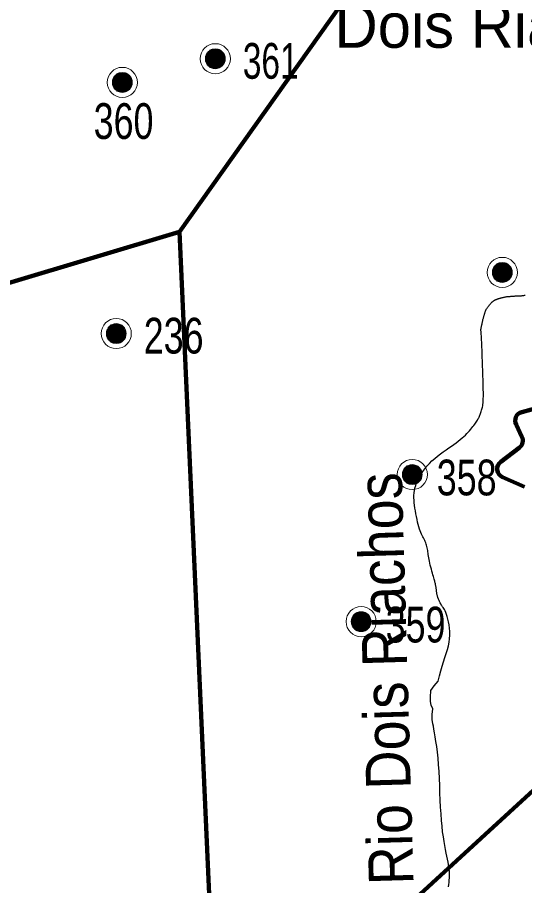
# Model space of a CAD drawing. Extents: x 553962 to 842807, y 8883888 to 9032388.
# Drawn here: x 703268 to 708947, y 8951050 to 8960766 of the extents above; entities that cross this region are included whole.
import ezdxf
from ezdxf.enums import TextEntityAlignment as Align

# ---------------------------------------------------------------- set-up
doc = ezdxf.new("R2010")
doc.units = 0
doc.header["$LTSCALE"] = 160
for name, color, linetype, lineweight in [('21', 7, 'Continuous', 25), ('22', 7, 'Continuous', 35), ('27', 7, 'Continuous', 90), ('32', 7, 'Continuous', 13), ('33', 7, 'Continuous', 13), ('7', 7, 'Continuous', 90)]:
    doc.layers.add(name, color=color, linetype=linetype, lineweight=lineweight)
doc.layers.add('29', color=7, linetype='Continuous')

msp = doc.modelspace()

# ---------------------------------------------------------------- linework, layer by layer
at = {"layer": '21'}
for points in [[(708437, 8956293.7), (708441.3, 8956303.2), (708445.5, 8956313.2), (708449.7, 8956323.7), (708453.8, 8956334.6), (708457.8, 8956345.8), (708461.7, 8956357.3), (708465.4, 8956369), (708468.9, 8956381), (708472.1, 8956393.1), (708475, 8956405.4), (708477.6, 8956418.6), (708479.8, 8956433.5), (708481.7, 8956451.1), (708483.1, 8956472), (708484.1, 8956497.2), (708484.6, 8956527.5), (708484.6, 8956563.7), (708484.1, 8956606.2), (708483.2, 8956654), (708481.8, 8956705.4), (708480.3, 8956759.1), (708478.5, 8956813.4), (708476.7, 8956866.9), (708474.8, 8956918), (708473.1, 8956965.2), (708471.5, 8957007.4), (708470, 8957044.6), (708468.7, 8957077.2), (708467.5, 8957105.9), (708466.3, 8957130.9), (708465.2, 8957152.8), (708464.2, 8957172), (708463.1, 8957189), (708462.1, 8957204.1), (708461.1, 8957217.7), (708460.1, 8957229.8), (708459.3, 8957240.7), (708458.7, 8957250.5), (708458.3, 8957259.4), (708458.2, 8957267.5), (708458.3, 8957275.2), (708458.9, 8957282.4), (708459.7, 8957289.3), (708460.8, 8957296), (708462.1, 8957302.5), (708463.6, 8957308.9), (708465.1, 8957315.2), (708466.7, 8957321.6), (708468.3, 8957328), (708469.8, 8957334.6), (708471.2, 8957341.3), (708472.7, 8957348.2), (708474.1, 8957355.1), (708475.6, 8957362.2), (708477.2, 8957369.4), (708478.8, 8957376.7), (708480.6, 8957384), (708482.5, 8957391.5), (708484.6, 8957398.9), (708486.7, 8957406.3), (708488.8, 8957413.7), (708490.9, 8957421), (708493, 8957428.1), (708495, 8957434.9), (708496.9, 8957441.6), (708498.7, 8957448), (708500.4, 8957454.1), (708502, 8957459.9), (708503.7, 8957465.6), (708505.4, 8957471.2), (708507.2, 8957476.6), (708509.3, 8957482), (708511.6, 8957487.3), (708514.1, 8957492.6), (708516.9, 8957497.9), (708520, 8957503.2), (708523.2, 8957508.4), (708526.6, 8957513.7), (708530.1, 8957518.8), (708533.6, 8957523.9), (708537.2, 8957529), (708540.8, 8957533.9), (708544.4, 8957538.8), (708548.1, 8957543.6), (708551.7, 8957548.3), (708555.4, 8957552.9), (708559.1, 8957557.3), (708562.9, 8957561.7), (708566.8, 8957565.8), (708570.7, 8957569.9), (708574.7, 8957573.8), (708578.7, 8957577.5), (708582.7, 8957581), (708586.8, 8957584.4), (708590.8, 8957587.5), (708594.7, 8957590.5), (708598.6, 8957593.2), (708602.5, 8957595.8), (708606.3, 8957598.1), (708610.1, 8957600.3)], [(708610.1, 8957600.3), (708613.9, 8957602.3), (708617.8, 8957604.2), (708621.9, 8957606), (708626.1, 8957607.8), (708630.4, 8957609.6), (708635, 8957611.3), (708639.8, 8957613.1), (708644.9, 8957614.8), (708650.2, 8957616.6), (708655.9, 8957618.4), (708661.8, 8957620.3), (708668.2, 8957622.2), (708674.8, 8957624.2), (708681.8, 8957626.2), (708689.2, 8957628.3), (708696.9, 8957630.4), (708704.8, 8957632.4), (708713, 8957634.4), (708721.5, 8957636.2), (708730.2, 8957637.9), (708739, 8957639.4), (708747.9, 8957640.7), (708757, 8957641.8), (708766, 8957642.8), (708774.9, 8957643.6), (708783.6, 8957644.3), (708792.1, 8957644.9), (708800.2, 8957645.4), (708807.8, 8957646), (708815, 8957646.5), (708821.7, 8957647), (708828, 8957647.5), (708834, 8957648), (708839.8, 8957648.5), (708845.3, 8957648.9), (708850.7, 8957649.2), (708856.1, 8957649.5), (708861.4, 8957649.7), (708866.8, 8957649.9), (708872.2, 8957650), (708877.6, 8957650.1), (708883.2, 8957650.2), (708888.8, 8957650.3), (708894.5, 8957650.5), (708900.4, 8957650.7), (708906.4, 8957651), (708912.5, 8957651.4), (708918.8, 8957651.9), (708925.2, 8957652.6), (708931.7, 8957653.4), (708938.3, 8957654.5), (708945, 8957655.8), (708951.8, 8957657.4)], [(707956, 8954384.1), (707954.9, 8954391.2), (707953.6, 8954398.5), (707952.2, 8954405.9), (707950.7, 8954413.4), (707949.1, 8954421), (707947.3, 8954428.8), (707945.3, 8954437.1), (707943, 8954446), (707940.4, 8954455.9), (707937.4, 8954466.9), (707933.9, 8954479.4), (707929.9, 8954493.6), (707925.3, 8954509.7), (707920.2, 8954528), (707914.5, 8954548.1), (707908.6, 8954569.4), (707902.5, 8954591.7), (707896.6, 8954614.5), (707890.9, 8954637.2), (707885.6, 8954659.4), (707881, 8954680.8), (707877.1, 8954701), (707873.8, 8954719.9), (707871.1, 8954737.8), (707868.7, 8954754.7), (707866.4, 8954770.9), (707864.2, 8954786.4), (707861.8, 8954801.5), (707859.2, 8954816.2), (707856.2, 8954830.6), (707852.6, 8954844.8), (707848.7, 8954858.9), (707844.3, 8954872.8), (707839.4, 8954886.5), (707834.1, 8954900.2), (707828.4, 8954913.7), (707822.2, 8954927.1), (707815.6, 8954940.5), (707808.6, 8954954.2), (707801.3, 8954968.6), (707793.8, 8954984.1), (707786.2, 8955000.9), (707778.5, 8955019.5), (707770.9, 8955040.3), (707763.3, 8955063.6), (707755.9, 8955089.6), (707748.8, 8955117.9), (707741.9, 8955148), (707735.5, 8955179.4), (707729.4, 8955211.4), (707724, 8955243.5), (707719, 8955275.2), (707714.8, 8955305.8), (707711.3, 8955335.1), (707708.8, 8955363.1), (707707.5, 8955390.3), (707707.6, 8955417.1), (707709.3, 8955443.8), (707713, 8955470.7), (707718.8, 8955498.4), (707727, 8955527), (707737.7, 8955556.9), (707751, 8955587.8), (707766.7, 8955619.4), (707784.9, 8955651.3), (707805.4, 8955683.3), (707828.1, 8955714.8), (707853.1, 8955745.7), (707880.1, 8955775.4), (707909.2, 8955803.8), (707939.8, 8955830.8), (707971.5, 8955856.6), (708003.7, 8955881.1), (708035.9, 8955904.5), (708067.7, 8955926.8), (708098.4, 8955948.1), (708127.7, 8955968.5), (708155, 8955988), (708180.5, 8956006.7), (708204.2, 8956024.7), (708226.2, 8956042.2), (708246.8, 8956059.2), (708265.9, 8956075.9), (708283.8, 8956092.2), (708300.4, 8956108.5), (708316.1, 8956124.6), (708330.7, 8956140.5), (708344.2, 8956156.1), (708356.8, 8956171.3), (708368.4, 8956185.9), (708378.9, 8956199.9), (708388.5, 8956213.1), (708397.1, 8956225.4), (708404.8, 8956236.7), (708411.5, 8956247.1), (708417.6, 8956257), (708423.1, 8956266.3), (708428, 8956275.5), (708432.6, 8956284.5), (708437, 8956293.7)], [(708079.3, 8954060.8), (708071.1, 8954085.7), (708063.2, 8954106.6), (708055.7, 8954124), (708048.6, 8954138.5), (708041.7, 8954150.6), (708035.2, 8954160.9), (708029.1, 8954169.9), (708023.1, 8954178.3), (708017.4, 8954186.5), (708012, 8954195), (708006.8, 8954203.9), (708001.8, 8954213), (707997.2, 8954222.1), (707992.8, 8954231.2), (707988.8, 8954240.2), (707985.1, 8954248.9), (707981.7, 8954257.1), (707978.7, 8954264.9), (707976, 8954272.2), (707973.6, 8954279.2), (707971.6, 8954285.9), (707969.7, 8954292.3), (707968.1, 8954298.6), (707966.8, 8954304.8), (707965.5, 8954311), (707964.5, 8954317.3), (707963.5, 8954323.6), (707962.7, 8954330.1), (707961.9, 8954336.5), (707961.2, 8954343.1), (707960.4, 8954349.7), (707959.7, 8954356.5), (707958.9, 8954363.2), (707958, 8954370.1), (707957.1, 8954377), (707956, 8954384.1)], [(708079.3, 8954060.8), (708071.1, 8954085.7), (708063.2, 8954106.6), (708055.7, 8954124), (708048.6, 8954138.5), (708041.7, 8954150.6), (708035.2, 8954160.9), (708029.1, 8954169.9), (708023.1, 8954178.3), (708017.4, 8954186.5), (708012, 8954195), (708006.8, 8954203.9), (708001.8, 8954213), (707997.2, 8954222.1), (707992.8, 8954231.2), (707988.8, 8954240.2), (707985.1, 8954248.9), (707981.7, 8954257.1), (707978.7, 8954264.9), (707976, 8954272.2), (707973.6, 8954279.2), (707971.6, 8954285.9), (707969.7, 8954292.3), (707968.1, 8954298.6), (707966.8, 8954304.8), (707965.5, 8954311), (707964.5, 8954317.3), (707963.5, 8954323.6), (707962.7, 8954330.1), (707961.9, 8954336.5), (707961.2, 8954343.1), (707960.4, 8954349.7), (707959.7, 8954356.5), (707958.9, 8954363.2), (707958, 8954370.1), (707957.1, 8954377), (707956, 8954384.1)], [(708105.3, 8951136), (708106, 8951160.4), (708105.7, 8951184.6), (708104.4, 8951208.7), (708102.1, 8951233.3), (708098.8, 8951258.8), (708094.7, 8951285.6), (708089.7, 8951314.1), (708083.8, 8951344.7), (708077, 8951378), (708069.6, 8951414.3), (708061.6, 8951454), (708053.2, 8951497.3), (708044.9, 8951544.7), (708036.7, 8951596.3), (708028.9, 8951652.5), (708021.8, 8951713.6), (708015.7, 8951780), (708010.6, 8951851.7), (708006.3, 8951927.7), (708002.7, 8952006.7), (707999.3, 8952087.6), (707996, 8952169.1), (707992.4, 8952249.9), (707988.2, 8952328.8), (707983.1, 8952404.7), (707977, 8952476.3), (707970, 8952543.3), (707962.4, 8952605.4), (707954.5, 8952662.4), (707946.5, 8952714.1), (707938.8, 8952760.1), (707931.6, 8952800.3), (707925.2, 8952834.3), (707919.7, 8952862.3), (707915.5, 8952885.6), (707912.4, 8952906.2), (707910.7, 8952925.7), (707910.4, 8952945.9), (707911.6, 8952968.7), (707914.4, 8952995.7), (707918.9, 8953028.8), (707901.9, 8953068.2), (707891.4, 8953109.1), (707891.4, 8953159.4), (707897.7, 8953232.7), (707934.3, 8953286.2), (707978.2, 8953339.4), (707992.2, 8953397.3), (708007.2, 8953453.2), (708022.7, 8953505.9), (708038.5, 8953555.7), (708053.9, 8953602.8), (708068.4, 8953647.8), (708081.6, 8953690.9), (708092.8, 8953732.6), (708101.7, 8953773.3), (708107.5, 8953813.5), (708110.1, 8953853.3), (708109.6, 8953892.4), (708106.6, 8953930.3), (708101.6, 8953966.7), (708095.1, 8954000.8), (708087.5, 8954032.4), (708079.3, 8954060.8)], [(708105.3, 8951136), (708106, 8951160.4), (708105.7, 8951184.6), (708104.4, 8951208.7), (708102.1, 8951233.3), (708098.8, 8951258.8), (708094.7, 8951285.6), (708089.7, 8951314.1), (708083.8, 8951344.7), (708077, 8951378), (708069.6, 8951414.3), (708061.6, 8951454), (708053.2, 8951497.3), (708044.9, 8951544.7), (708036.7, 8951596.3), (708028.9, 8951652.5), (708021.8, 8951713.6), (708015.7, 8951780), (708010.6, 8951851.7), (708006.3, 8951927.7), (708002.7, 8952006.7), (707999.3, 8952087.6), (707996, 8952169.1), (707992.4, 8952249.9), (707988.2, 8952328.8), (707983.1, 8952404.7), (707977, 8952476.3), (707970, 8952543.3), (707962.4, 8952605.4), (707954.5, 8952662.4), (707946.5, 8952714.1), (707938.8, 8952760.1), (707931.6, 8952800.3), (707925.2, 8952834.3), (707919.7, 8952862.3), (707915.5, 8952885.6), (707912.4, 8952906.2), (707910.7, 8952925.7), (707910.4, 8952945.9), (707911.6, 8952968.7), (707914.4, 8952995.7), (707918.9, 8953028.8), (707901.9, 8953068.2), (707891.4, 8953109.1), (707891.4, 8953159.4), (707897.7, 8953232.7), (707934.3, 8953286.2), (707978.2, 8953339.4), (707992.2, 8953397.3), (708007.2, 8953453.2), (708022.7, 8953505.9), (708038.5, 8953555.7), (708053.9, 8953602.8), (708068.4, 8953647.8), (708081.6, 8953690.9), (708092.8, 8953732.6), (708101.7, 8953773.3), (708107.5, 8953813.5), (708110.1, 8953853.3), (708109.6, 8953892.4), (708106.6, 8953930.3), (708101.6, 8953966.7), (708095.1, 8954000.8), (708087.5, 8954032.4), (708079.3, 8954060.8)], [(708095.8, 8951038.3), (708098.8, 8951062.2), (708101.5, 8951086.6), (708103.8, 8951111.3), (708105.3, 8951136)]]:
    msp.add_lwpolyline(points, dxfattribs=at)
at = {"layer": '27'}
for points in [[(691582, 8951218.7), (697371.2, 8956056), (705081.2, 8958366.8), (713138.6, 8969695)], [(705081.2, 8958366.8), (705509.2, 8948874.2), (720755.9, 8962863.6), (723053.6, 8963740.6)]]:
    msp.add_lwpolyline(points, dxfattribs=at)
at = {"layer": '32'}
for p, q in [((705424, 8960403), (705424, 8960203)), ((705434, 8960403), (705434, 8960203)), ((705444, 8960403), (705444, 8960203)), ((705454, 8960413), (705454, 8960193)), ((705464, 8960413), (705464, 8960193)), ((705474, 8960413), (705474, 8960193)), ((705484, 8960413), (705484, 8960193)), ((705494, 8960413), (705494, 8960193)), ((705504, 8960413), (705504, 8960193)), ((705514, 8960413), (705514, 8960193)), ((705524, 8960403), (705524, 8960203)), ((705534, 8960403), (705534, 8960203)), ((705374, 8960333), (705374, 8960273)), ((705384, 8960353), (705384, 8960253)), ((705394, 8960373), (705394, 8960233)), ((705404, 8960383), (705404, 8960223)), ((705414, 8960393), (705414, 8960213)), ((705544, 8960393), (705544, 8960213)), ((705554, 8960383), (705554, 8960223)), ((705564, 8960373), (705564, 8960233)), ((705574, 8960363), (705574, 8960243)), ((705584, 8960343), (705584, 8960263)), ((704353, 8960108), (704353, 8959968)), ((704363, 8960118), (704363, 8959958)), ((704373, 8960128), (704373, 8959948)), ((704383, 8960138), (704383, 8959938)), ((704393, 8960138), (704393, 8959938)), ((704403, 8960138), (704403, 8959938)), ((704413, 8960148), (704413, 8959928)), ((704423, 8960148), (704423, 8959928)), ((704433, 8960148), (704433, 8959928)), ((704443, 8960148), (704443, 8959928)), ((704453, 8960148), (704453, 8959928)), ((704463, 8960148), (704463, 8959928)), ((704473, 8960148), (704473, 8959928)), ((704483, 8960138), (704483, 8959938)), ((704493, 8960138), (704493, 8959938)), ((704503, 8960128), (704503, 8959948)), ((704513, 8960118), (704513, 8959958)), ((704523, 8960108), (704523, 8959968)), ((704333, 8960068), (704333, 8960008)), ((704343, 8960088), (704343, 8959988)), ((704533, 8960098), (704533, 8959978)), ((704543, 8960078), (704543, 8959998)), ((704285, 8957298), (704285, 8957158)), ((704295, 8957308), (704295, 8957148)), ((704305, 8957318), (704305, 8957138)), ((704315, 8957328), (704315, 8957128)), ((704325, 8957328), (704325, 8957128)), ((704335, 8957328), (704335, 8957128)), ((704345, 8957338), (704345, 8957118)), ((704355, 8957338), (704355, 8957118)), ((704365, 8957338), (704365, 8957118)), ((704375, 8957338), (704375, 8957118)), ((704385, 8957338), (704385, 8957118)), ((704395, 8957338), (704395, 8957118)), ((704405, 8957338), (704405, 8957118)), ((704415, 8957328), (704415, 8957128)), ((704425, 8957328), (704425, 8957128)), ((704435, 8957318), (704435, 8957138)), ((704445, 8957308), (704445, 8957148)), ((704455, 8957298), (704455, 8957158)), ((704465, 8957288), (704465, 8957168)), ((704265, 8957258), (704265, 8957198)), ((704275, 8957278), (704275, 8957178)), ((704475, 8957268), (704475, 8957188))]:
    msp.add_line(p, q, dxfattribs=at)
for centre, radius in [((705484, 8960303), 168.7), ((705484, 8960303), 111), ((704443, 8960038), 168.7), ((704443, 8960038), 111), ((704375, 8957228), 168.7), ((704375, 8957228), 111)]:
    msp.add_circle(centre, radius, dxfattribs=at)
at = {"layer": '33'}
for p, q in [((708607, 8957982), (708607, 8957842)), ((708617, 8957992), (708617, 8957832)), ((708627, 8958002), (708627, 8957822)), ((708637, 8958012), (708637, 8957812)), ((708647, 8958012), (708647, 8957812)), ((708657, 8958012), (708657, 8957812)), ((708667, 8958022), (708667, 8957802)), ((708677, 8958022), (708677, 8957802)), ((708687, 8958022), (708687, 8957802)), ((708697, 8958022), (708697, 8957802)), ((708707, 8958022), (708707, 8957802)), ((708717, 8958022), (708717, 8957802)), ((708727, 8958022), (708727, 8957802)), ((708737, 8958012), (708737, 8957812)), ((708747, 8958012), (708747, 8957812)), ((708757, 8958002), (708757, 8957822)), ((708767, 8957992), (708767, 8957832)), ((708777, 8957982), (708777, 8957842)), ((708787, 8957972), (708787, 8957852)), ((708587, 8957942), (708587, 8957882)), ((708597, 8957962), (708597, 8957862)), ((708797, 8957952), (708797, 8957872)), ((707619, 8955740), (707619, 8955560)), ((707629, 8955750), (707629, 8955550)), ((707639, 8955750), (707639, 8955550)), ((707649, 8955750), (707649, 8955550)), ((707659, 8955760), (707659, 8955540)), ((707669, 8955760), (707669, 8955540)), ((707679, 8955760), (707679, 8955540)), ((707689, 8955760), (707689, 8955540)), ((707699, 8955760), (707699, 8955540)), ((707709, 8955760), (707709, 8955540)), ((707719, 8955760), (707719, 8955540)), ((707729, 8955750), (707729, 8955550)), ((707739, 8955750), (707739, 8955550)), ((707749, 8955740), (707749, 8955560)), ((707579, 8955680), (707579, 8955620)), ((707589, 8955700), (707589, 8955600)), ((707599, 8955720), (707599, 8955580)), ((707609, 8955730), (707609, 8955570)), ((707759, 8955730), (707759, 8955570)), ((707769, 8955720), (707769, 8955580)), ((707779, 8955710), (707779, 8955590)), ((707789, 8955690), (707789, 8955610)), ((707037, 8954084), (707037, 8953924)), ((707047, 8954094), (707047, 8953914)), ((707057, 8954104), (707057, 8953904)), ((707067, 8954104), (707067, 8953904)), ((707077, 8954104), (707077, 8953904)), ((707087, 8954114), (707087, 8953894)), ((707097, 8954114), (707097, 8953894)), ((707107, 8954114), (707107, 8953894)), ((707117, 8954114), (707117, 8953894)), ((707127, 8954114), (707127, 8953894)), ((707137, 8954114), (707137, 8953894)), ((707147, 8954114), (707147, 8953894)), ((707157, 8954104), (707157, 8953904)), ((707167, 8954104), (707167, 8953904)), ((707177, 8954094), (707177, 8953914)), ((707187, 8954084), (707187, 8953924)), ((707007, 8954034), (707007, 8953974)), ((707017, 8954054), (707017, 8953954)), ((707027, 8954074), (707027, 8953934)), ((707197, 8954074), (707197, 8953934)), ((707207, 8954064), (707207, 8953944)), ((707217, 8954044), (707217, 8953964))]:
    msp.add_line(p, q, dxfattribs=at)
for centre, radius in [((708697, 8957912), 168.7), ((708697, 8957912), 111), ((707689, 8955650), 168.7), ((707689, 8955650), 111), ((707117, 8954004), 168.7), ((707117, 8954004), 111)]:
    msp.add_circle(centre, radius, dxfattribs=at)
at = {"layer": '7'}
for p, q in [((709470.2, 8956503), (708914.4, 8956349.1)), ((708851.1, 8956209.2), (708916.5, 8956073.8)), ((708886.8, 8955950.6), (708678.9, 8955793.2)), ((708699.4, 8955621.8), (708946.9, 8955514.2))]:
    msp.add_line(p, q, dxfattribs=at)
msp.add_arc((708739.3, 8955713.5), 100, 127.11747, 246.49677, dxfattribs=at)
for centre, major_axis, end_param in [((708941.1, 8956252.7), (-96.4, -26.7), 6.462947), ((708826.5, 8956030.3), (79.7, 60.3), 6.085405)]:
    msp.add_ellipse(centre, major_axis=major_axis, ratio=1, start_param=4.712389, end_param=end_param, dxfattribs=at)

# ---------------------------------------------------------------- texts
at = {"layer": '22', "width": 0.9}
msp.add_text('Rio Dois Riachos', height=500, rotation=91.671, dxfattribs=at).set_placement((707637.1, 8953371.6), align=Align.CENTER)
at = {"layer": '29'}
msp.add_text('Dois Riachos', height=500, dxfattribs=at).set_placement((706819.1, 8960425.8))
at = {"layer": '32'}
for s, width, p in [('361', 0.7, (705791.8, 8960079.3)), ('360', 0.75, (704122.2, 8959405.8)), ('236', 0.75, (704682.8, 8957004.3))]:
    msp.add_text(s, height=400, dxfattribs=dict(at, width=width)).set_placement(p)
at = {"layer": '33', "width": 0.75}
for s, p in [('358', (707963.2, 8955417.1)), ('359', (707391.2, 8953771.1))]:
    msp.add_text(s, height=400, dxfattribs=at).set_placement(p)

doc.saveas('drawing.dxf')
